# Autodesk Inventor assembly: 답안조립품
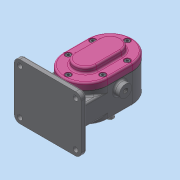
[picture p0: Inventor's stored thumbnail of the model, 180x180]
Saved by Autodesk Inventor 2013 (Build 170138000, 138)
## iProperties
Created: 2020-09
Part Number: 답안조립품
Document SubType Name: Assembly
Designer: dgall
Author: dgall
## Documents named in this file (11)
- C:\Users\dgall\Desktop\700906V1021\답안조립품.iam
- C:\Users\dgall\Desktop\700906V1021\본체.ipt
- C:\Users\dgall\Desktop\700906V1021\메인축.ipt
- C:\Users\dgall\Desktop\700906V1021\서브축.ipt
- C:\Users\dgall\Desktop\700906V1021\키 6 x 6 x 18.ipt
- C:\Users\dgall\Desktop\700906V1021\베어링부시.ipt
- C:\Users\dgall\Desktop\700906V1021\스퍼기어.ipt
- C:\Users\dgall\Desktop\700906V1021\개스킷.ipt
- C:\Users\dgall\Desktop\700906V1021\오일 실 16 28 7.ipt
- C:\Users\dgall\Desktop\700906V1021\커버.ipt
- C:\Users\dgall\Desktop\700906V1021\볼트 M5.ipt
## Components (1 placed, 1 different names)
1. 개스킷:1
